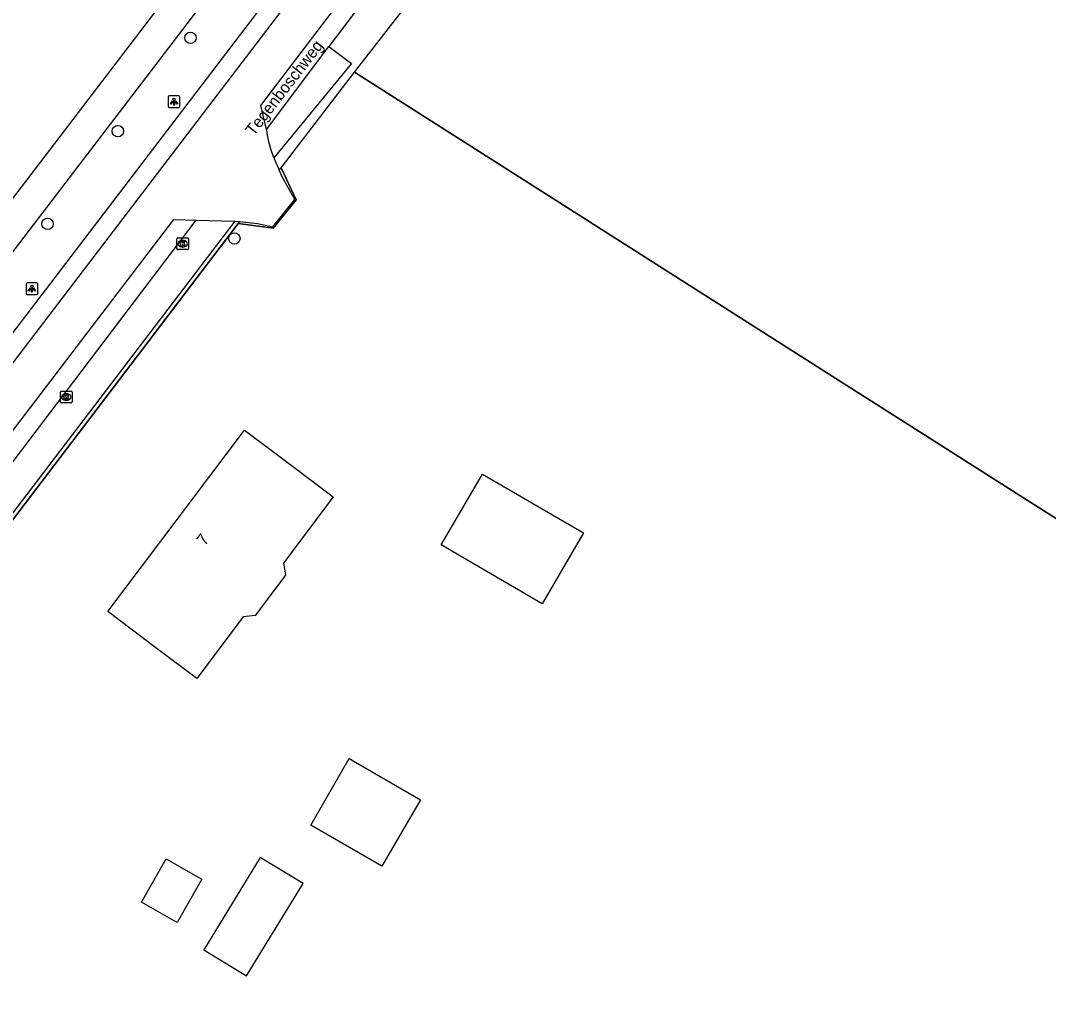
# Model space of a CAD drawing. Extents: x 156502 to 159074, y 384229 to 386094.
# Drawn here: x 157149.8 to 157237.7, y 385946.2 to 386030.2 of the extents above; entities that cross this region are included whole.
import ezdxf

# ---------------------------------------------------------------- set-up
doc = ezdxf.new("R2010")
doc.units = 0
for name, color, linetype in [('IMGEO_Berm_groen', 7, 'Continuous'), ('IMGEO_Berm_halfverhard', 7, 'Continuous'), ('IMGEO_Boom', 7, 'Continuous'), ('IMGEO_Gemengd_bos', 7, 'Continuous'), ('IMGEO_Groenvoorziening', 7, 'Continuous'), ('IMGEO_Haag', 7, 'Continuous'), ('IMGEO_Hek', 7, 'Continuous'), ('IMGEO_Kolk', 7, 'Continuous'), ('IMGEO_Lichtpunt', 7, 'Continuous'), ('IMGEO_Openbare_ruimte_label', 7, 'Continuous'), ('IMGEO_Pand', 7, 'Continuous'), ('IMGEO_Pand_nummerreeks', 7, 'Continuous'), ('IMGEO_Parkeervlak_open', 7, 'Continuous'), ('IMGEO_Rijbaan_lokaal_gesloten', 7, 'Continuous'), ('IMGEO_Rijbaan_lokaal_halfverhard', 7, 'Continuous')]:
    doc.layers.add(name, color=color, linetype=linetype)

msp = doc.modelspace()

# ---------------------------------------------------------------- linework, layer by layer
at = {"layer": 'IMGEO_Berm_groen'}
msp.add_lwpolyline([(157184.907, 386057.234), (157021.918, 385843.894)], dxfattribs=at)
at = {"layer": 'IMGEO_Berm_halfverhard'}
msp.add_lwpolyline([(157188.566, 386055.162), (157076.319, 385908.026), (157039.623, 385859.739), (157027.777, 385843.918)], dxfattribs=at)
at = {"layer": 'IMGEO_Boom'}
for centre in [(157164.36, 386028.715), (157158.164, 386020.734), (157152.156, 386012.808), (157168.114, 386011.561)]:
    msp.add_circle(centre, 0.489, dxfattribs=at)
at = {"layer": 'IMGEO_Gemengd_bos'}
for points in [[(157178.386, 386025.763), (157197.243, 386050.03), (157202.772, 386052.013)], [(157371.55, 385848.547), (157374.534, 385855.112), (157336.953, 385876.45), (157341.884, 385885.733), (157297.291, 385911.485), (157291.797, 385905.791), (157257.608, 385922.624), (157240.005, 385933.444), (157265.451, 385970.38), (157218.887, 386000), (157178.386, 386025.763)]]:
    msp.add_lwpolyline(points, dxfattribs=at)
at = {"layer": 'IMGEO_Groenvoorziening'}
for points in [[(157019.844, 385845.786), (157029.054, 385857.935), (157071.087, 385912.699), (157180.634, 386056.206), (157157.667, 386069.213), (157141.859, 386060.718)], [(157172.105, 386017.583), (157178.386, 386025.763)], [(157172.105, 386017.583), (157173.41, 386014.873), (157171.433, 386012.444), (157168.449, 386012.84)], [(157171.955, 386017.388), (157172.105, 386017.583)], [(157168.449, 386012.84), (157142.059, 385978.178)], [(157168.449, 386012.84), (157168.575, 386013.006)]]:
    msp.add_lwpolyline(points, dxfattribs=at)
at = {"layer": 'IMGEO_Haag'}
msp.add_lwpolyline([(157176.201, 386027.966), (157178.116, 386026.513), (157171.498, 386018.457)], dxfattribs=at)
at = {"layer": 'IMGEO_Hek'}
for points in [[(157173.41, 386014.873), (157172.105, 386017.583), (157178.386, 386025.763)], [(157178.386, 386025.763), (157218.887, 386000), (157265.451, 385970.38), (157240.005, 385933.444)], [(157171.433, 386012.444), (157173.41, 386014.873)], [(157142.059, 385978.178), (157168.449, 386012.84), (157171.433, 386012.444)]]:
    msp.add_lwpolyline(points, dxfattribs=at)
at = {"layer": 'IMGEO_Kolk'}
for p, q in [((157163.201, 386010.678), (157163.201, 386011.53)), ((157163.276, 386011.604), (157164.128, 386011.604)), ((157163.689, 386011.384), (157163.714, 386011.384)), ((157164.202, 386011.53), (157164.202, 386010.678)), ((157164.128, 386010.604), (157163.276, 386010.604)), ((157163.712, 386010.824), (157163.687, 386010.824)), ((157153.252, 385997.58), (157153.252, 385998.432)), ((157153.327, 385998.506), (157154.179, 385998.506)), ((157153.74, 385998.286), (157153.765, 385998.286)), ((157154.253, 385998.432), (157154.253, 385997.58)), ((157154.179, 385997.506), (157153.327, 385997.506)), ((157153.763, 385997.726), (157153.738, 385997.726))]:
    msp.add_line(p, q, dxfattribs=at)
for points in [[(157163.201, 386010.678), (157163.201, 386011.53)], [(157163.276, 386011.604), (157164.128, 386011.604)], [(157164.202, 386011.53), (157164.202, 386010.678)], [(157164.128, 386010.604), (157163.276, 386010.604)], [(157163.522, 386011.304), (157163.645, 386011.304), (157163.645, 386011.153), (157163.775, 386011.304), (157163.939, 386011.304), (157163.793, 386011.153), (157163.946, 386010.904), (157163.794, 386010.904), (157163.709, 386011.068), (157163.645, 386011.001), (157163.645, 386010.904), (157163.522, 386010.904), (157163.522, 386011.304)], [(157153.252, 385997.58), (157153.252, 385998.432)], [(157153.327, 385998.506), (157154.179, 385998.506)], [(157153.573, 385998.206), (157153.696, 385998.206), (157153.696, 385998.055), (157153.826, 385998.206), (157153.99, 385998.206), (157153.844, 385998.055), (157153.997, 385997.806), (157153.845, 385997.806), (157153.76, 385997.97), (157153.696, 385997.903), (157153.696, 385997.806), (157153.573, 385997.806), (157153.573, 385998.206)], [(157154.253, 385998.432), (157154.253, 385997.58)], [(157154.179, 385997.506), (157153.327, 385997.506)]]:
    msp.add_lwpolyline(points, dxfattribs=at)
for centre, start, end in [((157163.278, 386011.528), 91.55205, 178.44795), ((157163.278, 386011.528), 91.55205, 178.44795), ((157164.126, 386011.528), 1.55205, 88.44795), ((157164.126, 386011.528), 1.55205, 88.44795), ((157163.278, 386010.68), 181.55205, 268.44795), ((157163.278, 386010.68), 181.55205, 268.44795), ((157164.126, 386010.68), 271.55205, 358.44795), ((157164.126, 386010.68), 271.55205, 358.44795), ((157153.329, 385998.43), 91.55205, 178.44795), ((157153.329, 385998.43), 91.55205, 178.44795), ((157154.177, 385998.43), 1.55205, 88.44795), ((157154.177, 385998.43), 1.55205, 88.44795), ((157153.329, 385997.582), 181.55205, 268.44795), ((157153.329, 385997.582), 181.55205, 268.44795), ((157154.177, 385997.582), 271.55205, 358.44795), ((157154.177, 385997.582), 271.55205, 358.44795)]:
    msp.add_arc(centre, 0.0765, start, end, dxfattribs=at)
for centre, major_axis, ratio, start_param, end_param in [((157163.688, 386011.104), (-0.387, 0.002), 0.722429, 4.712389, 7.853982), ((157163.713, 386011.104), (-0.39, 0.002), 0.717154, 1.570796, 4.712389), ((157153.739, 385998.006), (-0.387, 0.002), 0.722429, 4.712389, 7.853982), ((157153.764, 385998.006), (-0.39, 0.002), 0.717154, 1.570796, 4.712389)]:
    msp.add_ellipse(centre, major_axis=major_axis, ratio=ratio, start_param=start_param, end_param=end_param, dxfattribs=at)
at = {"layer": 'IMGEO_Lichtpunt'}
for p, q in [((157162.467, 386023.668), (157162.467, 386022.861)), ((157162.467, 386023.668), (157162.467, 386022.861)), ((157163.369, 386023.763), (157162.561, 386023.763)), ((157163.369, 386023.763), (157162.561, 386023.763)), ((157163.463, 386022.861), (157163.463, 386023.668)), ((157163.463, 386022.861), (157163.463, 386023.668)), ((157162.561, 386022.767), (157163.369, 386022.767)), ((157162.561, 386022.767), (157163.369, 386022.767)), ((157150.317, 386007.677), (157150.317, 386006.87)), ((157150.317, 386007.677), (157150.317, 386006.87)), ((157151.219, 386007.772), (157150.411, 386007.772)), ((157151.219, 386007.772), (157150.411, 386007.772)), ((157151.313, 386006.87), (157151.313, 386007.677)), ((157151.313, 386006.87), (157151.313, 386007.677)), ((157150.411, 386006.776), (157151.219, 386006.776)), ((157150.411, 386006.776), (157151.219, 386006.776))]:
    msp.add_line(p, q, dxfattribs=at)
for points in [[(157162.841, 386023.332), (157162.88, 386023.304), (157162.692, 386023.042), (157162.654, 386023.069), (157162.841, 386023.332)], [(157162.943, 386023.284), (157162.99, 386023.284), (157162.99, 386022.962), (157162.943, 386022.962), (157162.943, 386023.284)], [(157163.053, 386023.304), (157163.091, 386023.331), (157163.278, 386023.069), (157163.239, 386023.041), (157163.053, 386023.304)], [(157150.691, 386007.341), (157150.73, 386007.313), (157150.542, 386007.051), (157150.504, 386007.078), (157150.691, 386007.341)], [(157150.793, 386007.293), (157150.84, 386007.293), (157150.84, 386006.971), (157150.793, 386006.971), (157150.793, 386007.293)], [(157150.903, 386007.313), (157150.941, 386007.34), (157151.128, 386007.078), (157151.089, 386007.05), (157150.903, 386007.313)]]:
    msp.add_lwpolyline(points, dxfattribs=at)
for centre in [(157162.966, 386023.466), (157150.816, 386007.475)]:
    msp.add_circle(centre, 0.0994, dxfattribs=at)
for centre, start, end in [((157162.561, 386023.668), 90, 180), ((157162.561, 386023.668), 90, 180), ((157163.369, 386023.668), 0, 90), ((157163.369, 386023.668), 0, 90), ((157162.561, 386022.861), 180, 270), ((157162.561, 386022.861), 180, 270), ((157163.369, 386022.861), 270, 0), ((157163.369, 386022.861), 270, 360), ((157150.411, 386007.677), 90, 180), ((157150.411, 386007.677), 90, 180), ((157151.219, 386007.677), 0, 90), ((157151.219, 386007.677), 0, 90), ((157150.411, 386006.87), 180, 270), ((157150.411, 386006.87), 180, 270), ((157151.219, 386006.87), 270, 0), ((157151.219, 386006.87), 270, 360)]:
    msp.add_arc(centre, 0.0946, start, end, dxfattribs=at)
at = {"layer": 'IMGEO_Pand'}
for points in [[(157172.309, 385983.796), (157172.477, 385982.769), (157169.891, 385979.334), (157168.858, 385979.21), (157164.901, 385973.952), (157161.306, 385976.659), (157157.311, 385979.666), (157168.986, 385995.174), (157172.981, 385992.165), (157176.572, 385989.461), (157172.309, 385983.796)], [(157194.436, 385980.334), (157185.797, 385985.358), (157189.317, 385991.411), (157197.956, 385986.387), (157194.436, 385980.334)], [(157174.646, 385961.409), (157177.942, 385967.095), (157184.018, 385963.573), (157180.722, 385957.887), (157174.646, 385961.409)], [(157170.335, 385958.652), (157165.499, 385950.756), (157169.155, 385948.516), (157173.991, 385956.413), (157170.335, 385958.652)], [(157163.228, 385953.08), (157162.985, 385953.218), (157162.765, 385953.343), (157160.179, 385954.81), (157162.282, 385958.518), (157164.571, 385957.219), (157165.089, 385956.926), (157165.332, 385956.788), (157163.228, 385953.08)]]:
    msp.add_lwpolyline(points, dxfattribs=at)
at = {"layer": 'IMGEO_Parkeervlak_open'}
msp.add_lwpolyline([(157168.146, 386013.05), (157147.947, 385986.527), (157147.422, 385986.929)], dxfattribs=at)
at = {"layer": 'IMGEO_Rijbaan_lokaal_gesloten'}
for points in [[(157170.869, 386020.883), (157170.373, 386022.922), (157193.363, 386053.168), (157195.745, 386055.945)], [(157189.916, 386054.397), (157077.656, 385907.175), (157041.694, 385859.803), (157028.972, 385842.844)], [(157171.498, 386018.457), (157171.955, 386017.388)], [(157168.575, 386013.006), (157170.093, 386012.849), (157171.41, 386012.563), (157173.283, 386014.882), (157172.189, 386016.84), (157171.955, 386017.388)], [(157090.505, 385918.168), (157162.952, 386013.182), (157164.84, 386013.11)], [(157164.84, 386013.11), (157168.146, 386013.05)], [(157168.146, 386013.05), (157168.575, 386013.006)]]:
    msp.add_lwpolyline(points, dxfattribs=at)
msp.add_arc((157178.911, 386021.674), 8.081, 185.61452, 203.45603, dxfattribs=at)
at = {"layer": 'IMGEO_Rijbaan_lokaal_halfverhard'}
for points in [[(157198.463, 386057.309), (157176.201, 386027.966)], [(157170.869, 386020.883), (157176.201, 386027.966)], [(157145.87, 385988.121), (157164.84, 386013.11)]]:
    msp.add_lwpolyline(points, dxfattribs=at)

# ---------------------------------------------------------------- texts
at = {"layer": 'IMGEO_Openbare_ruimte_label'}
msp.add_text('Tegenboschweg', height=1, rotation=52.27073, dxfattribs=at).set_placement((157169.767, 386020.263))
at = {"layer": 'IMGEO_Pand_nummerreeks'}
msp.add_text('7', height=1, rotation=53.02621, dxfattribs=at).set_placement((157165.603, 385985.227))

doc.saveas('drawing.dxf')
